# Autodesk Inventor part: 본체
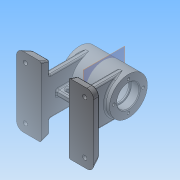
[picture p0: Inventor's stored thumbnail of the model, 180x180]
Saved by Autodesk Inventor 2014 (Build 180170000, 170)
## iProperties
Created: 2016-07
Part Number: 본체
Material: 일반
Document SubType Name: Modeling
Designer: net
Density: 1 g/cm^3
Appearance: 기본값
Author: net
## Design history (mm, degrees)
sketch "스케치1"
  geometry: C1 r 27 at (0, 0); 1 further point
  constraints: 1 centre point, 1 coincident
  dimensions: "d0" = 54 diameter of C1
extrude "돌출1" new body sketch "스케치1" stored distance "d1" = 70; taper "d2" = 0 deg
node "작업 평면1"
node "작업 평면2"
sketch "스케치2"
  geometry: L1 (0, 53.184)-(0, -53.184); L2 (-55, 50)-(-20, 50); L3 (-20, 50)-(-20, -50); L4 (-20, -50)-(-55, -50); L5 (-55, -50)-(-55, 50); L6 (55, 50)-(20, 50); L7 (20, 50)-(20, -50); L8 (55, -50)-(55, 50); L9 (20, -50)-(55, -50); 2 further points
  constraints: 18 end point, 4 symmetric about line, 2 parallel, 1 coincident, 1 horizontal, 1 midpoint, 1 perpendicular, 1 vertical
  dimensions: "d5" = 55 distance between parallel lines of L1 L5; "d6" = 100 distance between parallel lines of L4 L2; "d7" = 50 distance from line of L4 point (0, 0); "d8" = 35 distance between parallel lines of L5 L3; "d9" = 106.36812 distance of L1.start L1.end
extrude "돌출2" join sketch "스케치2" distance "d10" = 12; taper "d11" = 0 deg
sketch "스케치3"
  geometry: L1 (20, 50)-(20, -50) reference; L2 (20, 27)-(28, 27); L3 (28, 27)-(28, -27); L4 (28, -27)-(20, -27); L5 (20, -27)-(20, 27); 2 further points
  constraints: 8 end point, 2 midpoint, 2 parallel, 1 horizontal, 1 perpendicular
  dimensions: "d12" = 8 distance between parallel lines of L5 L3; "d13" = 54 distance between parallel lines of L4 L2
extrude "돌출3" join sketch "스케치3" stored distance "d14" = 12; taper "d15" = 0 deg
sketch "스케치4"
  geometry: C1 r 27 at (0, 0) reference; C2 r 16 at (0, 0)
  constraints: 1 centre point, 1 coincident
  dimensions: "d16" = 32 diameter of C2
extrude "돌출4" cut sketch "스케치4" distance "d17" = 12; taper "d18" = 0 deg
sketch "스케치5"
  geometry: C1 r 16 at (0, 0) reference; C2 r 14 at (0, 0)
  constraints: 1 centre point, 1 coincident
  dimensions: "d19" = 28 diameter of C2
extrude "돌출5" cut sketch "스케치5" distance "d20" = 2; taper "d21" = 0 deg
sketch "스케치6"
  geometry: C1 r 14 at (0, 0) reference; C2 r 22 at (0, 0)
  constraints: 1 centre point, 1 coincident
  dimensions: "d22" = 44 diameter of C2
extrude "돌출6" cut sketch "스케치6" distance "d23" = 42; taper "d24" = 0 deg
sketch "스케치7" dims "d25" = 42
  geometry: L1 (0, 0)-(0, 21); C1 r 27 at (0, 0) reference; 1 further point
  constraints: 2 coincident, 2 end point, 1 vertical, 1 vertical alignment, 2 other
hole "구멍1" sketch "스케치7" at (0, 21) diameter "d26" = 4; stored, may be unused: countersink angle "d30" = 90 deg, drill point angle "d32" = 118 deg; dims "d27" = 6, "d28" = 4, "d29" = 2, "d31" = 10
feature "스레드1" dims "d33" = 8, "d34" = 0
feature "스레드2" dims "d38" = 8, "d39" = 0
sketch "스케치8"
  geometry: L1 (-35, -27)-(35, -27) reference; L2 (-27.796, -27)-(27.796, -27); L3 (27.796, -27)-(27.796, -48); L4 (27.796, -48)-(-27.796, -48); L5 (-27.796, -48)-(-27.796, -27); 2 further points
  constraints: 8 end point, 2 midpoint, 2 parallel, 1 horizontal, 1 perpendicular
  dimensions: "d43" = 21 distance of L4.end L2.start; "d44" = 55.59245 distance between parallel lines of L5 L3
extrude "돌출7" join sketch "스케치8" stored distance "d45" = 8; taper "d46" = 0 deg
fillet "모깎기1" dims "d47" = 2
sketch "스케치9"
  geometry: L1 (-18, -29)-(18, -29) reference; L2 (18, -46)-(-18, -46) reference; L3 (18, -29)-(18, -46) reference; L4 (0, -29)-(0, -46); L5 (-18, -48)-(18, -48) reference; L6 (-11.5, -34.5)-(11.5, -34.5); L7 (-11.5, -41.5)-(11.5, -41.5); L8 (20, -70)-(55, -70) reference; A1 r 3.5 centre (-11.5, -38) between (-11.5, -34.5) and (-11.5, -41.5); A2 r 3.5 centre (11.5, -38) between (11.5, -41.5) and (11.5, -34.5); 1 further point
  constraints: 6 end point, 4 point on circle, 2 centre point, 2 midpoint, 2 tangent, 1 horizontal alignment, 1 parallel, 1 perpendicular
  dimensions: "d48" = 7 diameter of A1; "d49" = 7 diameter of A2; "d50" = 11.5 distance from line of A1.centre L4; "d139" = 32 distance from line of L8 A2.centre; "d140" = 23 distance of A1.centre A2.centre
extrude "돌출8" cut sketch "스케치9" stored distance "d54" = 8; taper "d55" = 0 deg
fillet "모깎기2" dims "d56" = 2
node "작업 평면3"
sketch "스케치10"
  geometry: 1 further point
sketch "스케치11"
  geometry: L1 (-35, 27)-(-35, -27) reference; C1 r 5 at (-13, 0); 1 further point
  constraints: 1 centre point
  dimensions: "d59" = 10 diameter of C1; "d62" = 13 distance of point (0, 0) C1.centre; "d63" = 22 distance from line of L1 C1.centre
extrude "돌출9" join sketch "스케치11" stored distance "d64" = 8; taper "d65" = 0 deg
hole "구멍2" diameter "d68" = 5.188; stored, may be unused: countersink angle "d72" = 90 deg, drill point angle "d74" = 118 deg; dims "d66" = 10, "d67" = 10, "d69" = 10, "d70" = 4, "d71" = 2, "d73" = 10
sketch "스케치12"
  geometry: L1 (0, 0)-(0, -27); L2 (0, 0)-(15.898, -25.441); L3 (0, 0)-(30, 0); 1 further point
  constraints: 6 end point, 1 equal length, 1 horizontal, 1 vertical, 1 vertical alignment, 1 other
  dimensions: "d75" = 30 distance of L1.start L2.end; "d76" = 58 deg angle of L2 L3
node "작업 평면4"
sketch "스케치13"
  geometry: C1 r 6 at (0, 0); 1 further point
  constraints: 1 centre point, 1 coincident
  dimensions: "d77" = 12 diameter of C1
extrude "돌출10" join sketch "스케치13" stored distance "d78" = 8; taper "d79" = 0 deg
hole "구멍3" diameter "d82" = 5.188; stored, may be unused: countersink angle "d86" = 90 deg, drill point angle "d88" = 118 deg; dims "d80" = 10, "d81" = 10, "d83" = 10, "d84" = 4, "d85" = 2, "d87" = 10
node "작업 평면5"
fillet "모깎기3" dims "d94" = 2
fillet "모깎기4" dims "d95" = 2
chamfer "모따기1" distance "d96" = 1; stored, may be unused: second distance "d97" = 2, angle "d98" = 45 deg
chamfer "모따기2" distance "d99" = 1; stored, may be unused: second distance "d100" = 2, angle "d101" = 45 deg
node "작업 평면7"
sketch "스케치15"
  geometry: L1 (-35, 27)-(-35, -27) reference; L2 (35, 27)-(-35, 27) reference; 2 further points
  constraints: 1 other
  dimensions: "d107" = 35 distance from line of L1 point (0, 0); "d108" = 27 distance from line of L2 point (0, 0)
feature "엠보싱2" sketch "스케치15" dims "d5" = 55, "d6" = 100, "d7" = 50, "d8" = 35, "d9" = 106.36812, "d109" = 0.5, "d110" = 0
feature "면 기울기1" dims angle "d111" = 20 deg
feature "면 기울기2" dims angle "d112" = 20 deg
node "작업 평면9"
sketch "스케치16"
  geometry: L1 (100, 12)-(0, 12) reference; L2 (100, 0)-(100, 12) reference; L3 (100, 0)-(107, 0); L4 (100, 0)-(95.632, 12); L5 (100, 0)-(124.389, 0); L6 (95.632, 12)-(100, 12); L7 (100, 12)-(100, 0); 1 further point
  constraints: 10 end point, 2 collinear, 2 horizontal, 1 point on line
  dimensions: "d116" = 110 deg angle of L5 L4
extrude "돌출11" cut sketch "스케치16" stored distance "d117" = 10; taper "d118" = 0 deg
sketch "스케치17"
  geometry: L1 (95.632, 12)-(0, 12) reference; L2 (0, 0)-(0, 12) reference; L3 (0, 0)-(4.368, 12); L4 (0, 0)-(34.429, 0); L5 (4.368, 12)-(0, 12); L6 (0, 0)-(0, 12); 1 further point
  constraints: 8 end point, 1 collinear, 1 horizontal, 1 perpendicular, 1 point on line
  dimensions: "d119" = 70 deg angle of L4 L3
extrude "돌출12" cut sketch "스케치17" stored distance "d120" = 10; taper "d121" = 0 deg
fillet "모깎기5" dims "d122" = 10
fillet "모깎기7" dims "d124" = 10
fillet "모깎기6" dims "d123" = 10
fillet "모깎기8" dims "d125" = 2
fillet "모깎기9" dims "d126" = 2
fillet "모깎기10" dims "d127" = 0.3
fillet "모깎기11" dims "d128" = 0.3
fillet "모깎기12" dims "d129" = 3
sketch "스케치18"
  geometry: L1 (-49.232, -36.714)-(-49.232, 36.714) reference; L2 (-43.802, 37.5)-(-27.102, 37.5); L3 (-42.5, 40.094)-(-42.5, 21.811); L4 (-55, 40.603)-(-55, -40.603) reference; L5 (-20, 50)-(-45.603, 50) reference; C1 r 5 at (-42.5, 37.5); C2 r 3 at (-42.5, 37.5); 1 further point
  constraints: 4 end point, 2 centre point, 2 perpendicular, 2 point on line, 1 coincident
  dimensions: "d130" = 12.5 distance between parallel lines of L4 L3; "d131" = 12.5 distance between parallel lines of L2 L5; "d132" = 10 diameter of C1; "d133" = 6 diameter of C2
extrude "돌출13" cut sketch "스케치18" distance "d134" = 4; taper "d135" = 0 deg
extrude "돌출14" cut sketch "스케치18" stored distance "d136" = 4; taper "d137" = 0 deg
fillet "모깎기13" dims "d138" = 2
node "솔리드1"
mirror "대칭1"
mirror "대칭2"
pattern_circular "원형 패턴1" dims angle "d36" = 360 deg
mirror "대칭3"
pattern_circular "원형 패턴2" dims "d41" = 360 deg
mirror "대칭4"
mirror "대칭5"
mirror "대칭6"
mirror "대칭7"
node "작업 평면8"
other parameters: "d89" = 27, "d103" = -27, "d113" = -35
